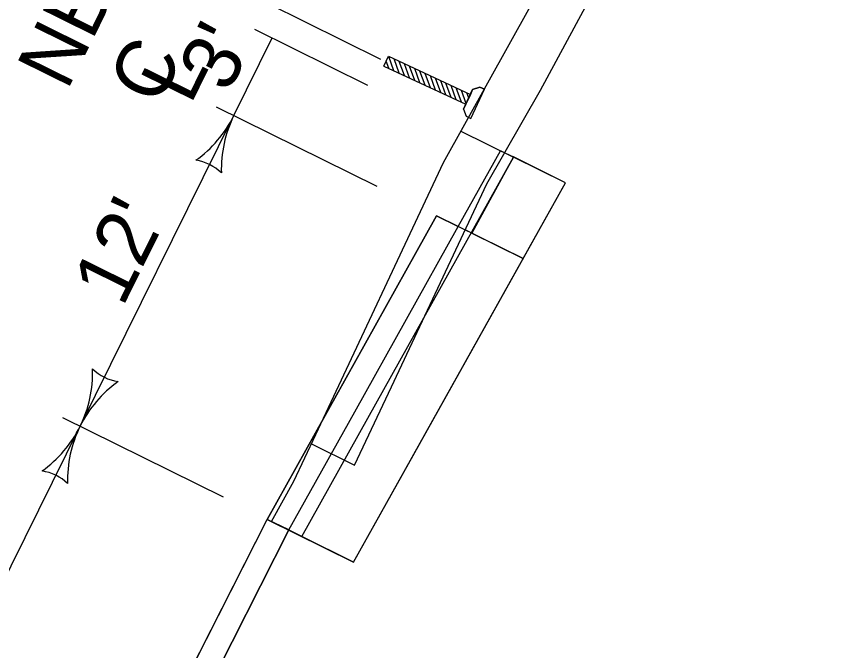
# Model space of a CAD drawing. Extents: x 14104283 to 14120882, y 8635219 to 8671666.
# Drawn here: x 14118276.9 to 14118389.3, y 8668626.9 to 8668714.8 of the extents above; entities that cross this region are included whole.
import ezdxf

# ---------------------------------------------------------------- set-up
doc = ezdxf.new("R2010")
doc.units = 0
for name, color, linetype in [('Cell', 7, 'Continuous'), ('Default', 7, 'Continuous'), ('dsnCellElements', 7, 'Continuous'), ('dsnShadingPaved', 7, 'Continuous'), ('dsnStgShadingPrevPav', 7, 'Continuous'), ('dsnTextFinalPlan', 7, 'Continuous'), ('TC_Subbase', 7, 'Continuous'), ('TC_SubgradeTreatment', 7, 'Continuous'), ('TC_SubstrataExistingPavement', 7, 'Continuous'), ('Terrain', 7, 'Continuous')]:
    doc.layers.add(name, color=color, linetype=linetype)

# ---------------------------------------------------------------- blocks, each defined once
blk = doc.blocks.new('LT')
at = {"layer": 'dsnCellElements'}
for centre, radius, start, end in [((-3.564, 0), 1.642, 342.2666, 17.7333), ((0, 4.25), 4.25, 241.9275, 270), ((0, -4.25), 4.25, 90, 118.0725)]:
    blk.add_arc(centre, radius, start, end, dxfattribs=at)

msp = doc.modelspace()

# ---------------------------------------------------------------- linework, layer by layer
at = {"layer": 'Cell'}
for p, q in [((14118327.84, 8668707.89), (14118328.47, 8668709.24)), ((14118328.51, 8668707.58), (14118328.15, 8668708.57)), ((14118328.47, 8668709.24), (14118339.81, 8668703.94)), ((14118329.23, 8668707.24), (14118328.52, 8668709.21)), ((14118329.95, 8668706.91), (14118329.24, 8668708.88)), ((14118330.67, 8668706.57), (14118329.95, 8668708.54)), ((14118331.39, 8668706.24), (14118330.67, 8668708.21)), ((14118327.84, 8668707.89), (14118339.18, 8668702.6)), ((14118332.11, 8668705.9), (14118331.39, 8668707.87)), ((14118332.83, 8668705.56), (14118332.11, 8668707.54)), ((14118333.55, 8668705.23), (14118332.83, 8668707.2)), ((14118334.27, 8668704.89), (14118333.55, 8668706.87)), ((14118334.98, 8668704.56), (14118334.27, 8668706.53)), ((14118335.7, 8668704.22), (14118334.99, 8668706.19)), ((14118336.42, 8668703.89), (14118335.71, 8668705.86)), ((14118337.14, 8668703.55), (14118336.42, 8668705.52)), ((14118337.86, 8668703.22), (14118337.14, 8668705.19)), ((14118338.58, 8668702.88), (14118337.86, 8668704.85)), ((14118341.1, 8668704.98), (14118340.12, 8668704.62)), ((14118340.12, 8668704.62), (14118341.1, 8668704.98)), ((14118341.77, 8668704.67), (14118341.1, 8668704.98)), ((14118341.1, 8668704.98), (14118341.77, 8668704.67)), ((14118339.23, 8668702.72), (14118338.58, 8668704.52)), ((14118338.87, 8668701.93), (14118340.12, 8668704.62)), ((14118339.81, 8668703.94), (14118339.18, 8668702.6)), ((14118339.57, 8668703.44), (14118339.3, 8668704.18)), ((14118340.12, 8668704.62), (14118339.81, 8668703.94)), ((14118339.89, 8668700.63), (14118341.77, 8668704.67)), ((14118339.89, 8668700.63), (14118341.77, 8668704.67)), ((14118339.18, 8668702.6), (14118338.87, 8668701.93)), ((14118338.87, 8668701.93), (14118339.22, 8668700.94)), ((14118338.87, 8668701.93), (14118339.22, 8668700.94)), ((14118339.22, 8668700.94), (14118339.89, 8668700.63)), ((14118339.22, 8668700.94), (14118339.89, 8668700.63))]:
    msp.add_line(p, q, dxfattribs=at)
at = {"layer": 'Default'}
for p, q in [((14118335.14, 8668687.15), (14118338.13, 8668685.68)), ((14118314.68, 8668643.65), (14118311.69, 8668645.12))]:
    msp.add_line(p, q, dxfattribs=at)
for points in [[(14118311.69, 8668645.12), (14118320.83, 8668661.5), (14118335.14, 8668687.15)], [(14118314.68, 8668643.65), (14118323.81, 8668660.02), (14118338.13, 8668685.68)]]:
    msp.add_lwpolyline(points, dxfattribs=at)
at = {"layer": 'dsnShadingPaved'}
for points in [[(14118338.13, 8668685.68), (14118343.98, 8668696.17), (14118345.79, 8668695.32), (14118340, 8668684.75)], [(14118347.09, 8668681.24), (14118352.95, 8668691.74), (14118345.77, 8668695.28), (14118339.92, 8668684.79)], [(14118311.69, 8668645.12), (14118323.63, 8668639.18), (14118347.09, 8668681.24), (14118335.14, 8668687.15)]]:
    msp.add_lwpolyline(points, close=True, dxfattribs=at)
at = {"layer": 'dsnStgShadingPrevPav'}
msp.add_lwpolyline([(14118287.17, 8668596.29), (14118289.97, 8668602.25), (14118311.69, 8668645.12), (14118314.68, 8668643.65), (14118302.91, 8668620.41), (14118292.96, 8668600.77), (14118290.16, 8668594.81)], close=True, dxfattribs=at)
at = {"layer": 'dsnTextFinalPlan'}
for p, q in [((14118311.71, 8668716.59), (14118327.37, 8668708.85)), ((14118309.93, 8668713), (14118325.59, 8668705.26)), ((14118307.07, 8668701.03), (14118312.39, 8668711.79)), ((14118304.62, 8668702.25), (14118326.85, 8668691.25)), ((14118285.79, 8668658.01), (14118307.07, 8668701.03)), ((14118283.34, 8668659.22), (14118305.57, 8668648.23)), ((14118264.52, 8668614.98), (14118285.79, 8668658.01))]:
    msp.add_line(p, q, dxfattribs=at)
at = {"layer": 'TC_Subbase'}
for p, q in [((14118338.5, 8668698.88), (14118345.77, 8668695.28)), ((14118314.68, 8668643.65), (14118316.42, 8668642.78))]:
    msp.add_line(p, q, dxfattribs=at)
msp.add_lwpolyline([(14118316.47, 8668642.76), (14118325.61, 8668659.13), (14118345.77, 8668695.28)], dxfattribs=at)
at = {"layer": 'TC_SubgradeTreatment'}
for p, q in [((14118352.95, 8668691.74), (14118345.79, 8668695.32)), ((14118323.63, 8668639.18), (14118316.47, 8668642.76))]:
    msp.add_line(p, q, dxfattribs=at)
msp.add_lwpolyline([(14118323.63, 8668639.18), (14118332.76, 8668655.55), (14118352.95, 8668691.74)], dxfattribs=at)
at = {"layer": 'TC_SubstrataExistingPavement'}
msp.add_line((14118314.68, 8668643.65), (14118311.69, 8668645.12), dxfattribs=at)
for points in [[(14118317.8, 8668655.57), (14118323.78, 8668652.61), (14118328.88, 8668663.48), (14118342.07, 8668691.57), (14118349.51, 8668704.57), (14118365.08, 8668733.42), (14118363.29, 8668734.31)], [(14118292.96, 8668600.77), (14118302.91, 8668620.41), (14118314.68, 8668643.65)]]:
    msp.add_lwpolyline(points, dxfattribs=at)
at = {"layer": 'Terrain'}
for points in [[(14118312.3, 8668644.82), (14118315.38, 8668650.41), (14118318.4, 8668656.85), (14118336.09, 8668694.53), (14118351.32, 8668721.95), (14118359.1, 8668736.38), (14118371.8, 8668757.81), (14118379.34, 8668769.44), (14118400.6, 8668797.95), (14118408.04, 8668806.8), (14118456.58, 8668898.64)], [(14118289.97, 8668602.25), (14118299.92, 8668621.89), (14118311.69, 8668645.12)]]:
    msp.add_lwpolyline(points, dxfattribs=at)

# ---------------------------------------------------------------- block references
at = {"layer": 'dsnTextFinalPlan'}
for p, xscale, yscale, rotation in [((14118307.07, 8668701.03), 3.942400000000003, 3.9424000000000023, 63.69110745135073), ((14118285.79, 8668658.01), 3.942400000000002, 3.9424000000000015, -116.30889254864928), ((14118285.79, 8668658.01), 3.942400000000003, 3.9424000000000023, 63.69110745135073)]:
    msp.add_blockref('LT', p, dxfattribs=dict(at, xscale=xscale, yscale=yscale, rotation=rotation))

# ---------------------------------------------------------------- texts
for s, p in [('NB', (14118284, 8668704.36)), ("3'", (14118306.31, 8668703.97)), ('C', (14118296.63, 8668702.15)), ('L', (14118301.07, 8668702.4)), ("12'", (14118291.67, 8668674.37))]:
    msp.add_text(s, height=8, rotation=63.6911, dxfattribs=at).set_placement(p)

doc.saveas('drawing.dxf')
